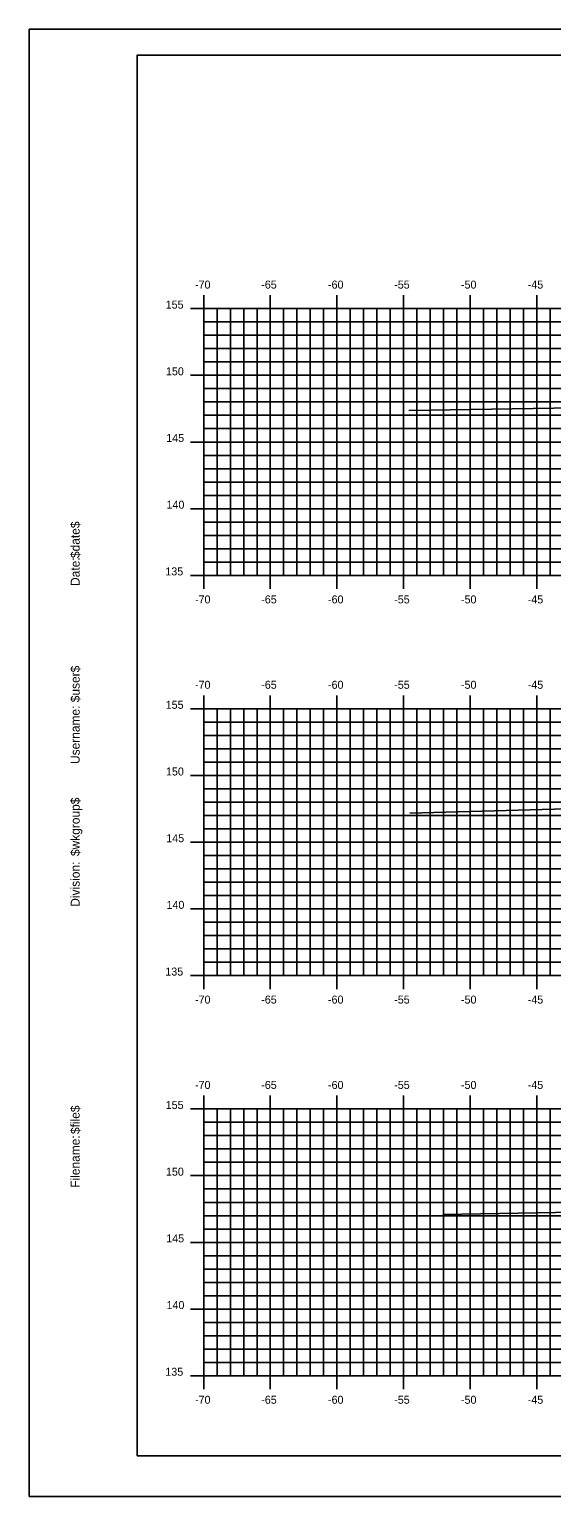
# Model space of a CAD drawing. Extents: x 1146968 to 1147138, y 608981 to 609091.
# Drawn here: x 1146968.1 to 1147007.3, y 608981.3 to 609091.3 of the extents above; entities that cross this region are included whole.
import ezdxf

# ---------------------------------------------------------------- set-up
doc = ezdxf.new("R2010")
doc.units = 0
for name, color, linetype in [('BORDER', 7, 'Continuous'), ('H_V ANNOTATION', 7, 'Continuous'), ('MAJOR', 7, 'Continuous'), ('MINOR', 7, 'Continuous'), ('PLOT BOUNDARY', 7, 'Continuous'), ('S_Roadway_Centerline', 7, 'Continuous')]:
    doc.layers.add(name, color=color, linetype=linetype)

msp = doc.modelspace()

# ---------------------------------------------------------------- linework, layer by layer
at = {"layer": 'BORDER'}
msp.add_lwpolyline([(1146976.18, 608984.34), (1147136.18, 608984.34), (1147136.18, 609089.34), (1146976.18, 609089.34)], close=True, dxfattribs=at)
at = {"layer": 'MAJOR'}
for p, q in [((1146981.18, 609071.34), (1146981.18, 609070.34)), ((1146986.18, 609071.34), (1146986.18, 609070.34)), ((1146991.18, 609071.34), (1146991.18, 609070.34)), ((1146996.18, 609071.34), (1146996.18, 609070.34)), ((1147001.18, 609071.34), (1147001.18, 609070.34)), ((1147006.18, 609071.34), (1147006.18, 609070.34)), ((1146980.18, 609070.34), (1146981.18, 609070.34)), ((1146981.18, 609070.34), (1147121.18, 609070.34)), ((1146981.18, 609050.34), (1146981.18, 609070.34)), ((1146981.18, 609050.34), (1146981.18, 609070.34)), ((1146981.18, 609070.34), (1147121.18, 609070.34)), ((1146986.18, 609050.34), (1146986.18, 609070.34)), ((1146991.18, 609050.34), (1146991.18, 609070.34)), ((1146996.18, 609050.34), (1146996.18, 609070.34)), ((1147001.18, 609050.34), (1147001.18, 609070.34)), ((1147006.18, 609050.34), (1147006.18, 609070.34)), ((1146980.18, 609065.34), (1146981.18, 609065.34)), ((1146981.18, 609065.34), (1147121.18, 609065.34)), ((1146980.18, 609060.34), (1146981.18, 609060.34)), ((1146981.18, 609060.34), (1147121.18, 609060.34)), ((1146980.18, 609055.34), (1146981.18, 609055.34)), ((1146981.18, 609055.34), (1147121.18, 609055.34)), ((1146980.18, 609050.34), (1146981.18, 609050.34)), ((1146981.18, 609050.34), (1147121.18, 609050.34)), ((1146981.18, 609050.34), (1147121.18, 609050.34)), ((1146981.18, 609049.33), (1146981.18, 609050.34)), ((1146986.18, 609049.33), (1146986.18, 609050.34)), ((1146991.18, 609049.33), (1146991.18, 609050.34)), ((1146996.18, 609049.33), (1146996.18, 609050.34)), ((1147001.18, 609049.33), (1147001.18, 609050.34)), ((1147006.18, 609049.33), (1147006.18, 609050.34)), ((1146980.18, 609040.34), (1146981.18, 609040.34)), ((1146981.18, 609041.34), (1146981.18, 609040.34)), ((1146981.18, 609040.34), (1147121.18, 609040.34)), ((1146981.18, 609020.34), (1146981.18, 609040.34)), ((1146981.18, 609020.34), (1146981.18, 609040.34)), ((1146981.18, 609040.34), (1147121.18, 609040.34)), ((1146986.18, 609041.34), (1146986.18, 609040.34)), ((1146986.18, 609020.34), (1146986.18, 609040.34)), ((1146991.18, 609041.34), (1146991.18, 609040.34)), ((1146991.18, 609020.34), (1146991.18, 609040.34)), ((1146996.18, 609041.34), (1146996.18, 609040.34)), ((1146996.18, 609020.34), (1146996.18, 609040.34)), ((1147001.18, 609041.34), (1147001.18, 609040.34)), ((1147001.18, 609020.34), (1147001.18, 609040.34)), ((1147006.18, 609041.34), (1147006.18, 609040.34)), ((1147006.18, 609020.34), (1147006.18, 609040.34)), ((1146980.18, 609035.34), (1146981.18, 609035.34)), ((1146981.18, 609035.34), (1147121.18, 609035.34)), ((1146980.18, 609030.34), (1146981.18, 609030.34)), ((1146981.18, 609030.34), (1147121.18, 609030.34)), ((1146980.18, 609025.34), (1146981.18, 609025.34)), ((1146981.18, 609025.34), (1147121.18, 609025.34)), ((1146980.18, 609020.34), (1146981.18, 609020.34)), ((1146981.18, 609020.34), (1147121.18, 609020.34)), ((1146981.18, 609020.34), (1147121.18, 609020.34)), ((1146981.18, 609019.33), (1146981.18, 609020.34)), ((1146986.18, 609019.33), (1146986.18, 609020.34)), ((1146991.18, 609019.33), (1146991.18, 609020.34)), ((1146996.18, 609019.33), (1146996.18, 609020.34)), ((1147001.18, 609019.33), (1147001.18, 609020.34)), ((1147006.18, 609019.33), (1147006.18, 609020.34)), ((1146981.18, 609011.34), (1146981.18, 609010.34)), ((1146986.18, 609011.34), (1146986.18, 609010.34)), ((1146991.18, 609011.34), (1146991.18, 609010.34)), ((1146996.18, 609011.34), (1146996.18, 609010.34)), ((1147001.18, 609011.34), (1147001.18, 609010.34)), ((1147006.18, 609011.34), (1147006.18, 609010.34)), ((1146980.18, 609010.34), (1146981.18, 609010.34)), ((1146981.18, 609010.34), (1147121.18, 609010.34)), ((1146981.18, 608990.34), (1146981.18, 609010.34)), ((1146981.18, 608990.34), (1146981.18, 609010.34)), ((1146981.18, 609010.34), (1147121.18, 609010.34)), ((1146986.18, 608990.34), (1146986.18, 609010.34)), ((1146991.18, 608990.34), (1146991.18, 609010.34)), ((1146996.18, 608990.34), (1146996.18, 609010.34)), ((1147001.18, 608990.34), (1147001.18, 609010.34)), ((1147006.18, 608990.34), (1147006.18, 609010.34)), ((1146980.18, 609005.34), (1146981.18, 609005.34)), ((1146981.18, 609005.34), (1147121.18, 609005.34)), ((1146980.18, 609000.34), (1146981.18, 609000.34)), ((1146981.18, 609000.34), (1147121.18, 609000.34)), ((1146980.18, 608995.34), (1146981.18, 608995.34)), ((1146981.18, 608995.34), (1147121.18, 608995.34)), ((1146980.18, 608990.34), (1146981.18, 608990.34)), ((1146981.18, 608990.34), (1147121.18, 608990.34)), ((1146981.18, 608990.34), (1147121.18, 608990.34)), ((1146981.18, 608989.33), (1146981.18, 608990.34)), ((1146986.18, 608989.33), (1146986.18, 608990.34)), ((1146991.18, 608989.33), (1146991.18, 608990.34)), ((1146996.18, 608989.33), (1146996.18, 608990.34)), ((1147001.18, 608989.33), (1147001.18, 608990.34)), ((1147006.18, 608989.33), (1147006.18, 608990.34))]:
    msp.add_line(p, q, dxfattribs=at)
at = {"layer": 'MINOR'}
for p, q in [((1146982.18, 609050.34), (1146982.18, 609070.34)), ((1146983.18, 609050.34), (1146983.18, 609070.34)), ((1146984.18, 609050.34), (1146984.18, 609070.34)), ((1146985.18, 609050.34), (1146985.18, 609070.34)), ((1146987.18, 609050.34), (1146987.18, 609070.34)), ((1146988.18, 609050.34), (1146988.18, 609070.34)), ((1146989.18, 609050.34), (1146989.18, 609070.34)), ((1146990.18, 609050.34), (1146990.18, 609070.34)), ((1146992.18, 609050.34), (1146992.18, 609070.34)), ((1146993.18, 609050.34), (1146993.18, 609070.34)), ((1146994.18, 609050.34), (1146994.18, 609070.34)), ((1146995.18, 609050.34), (1146995.18, 609070.34)), ((1146997.18, 609050.34), (1146997.18, 609070.34)), ((1146998.18, 609050.34), (1146998.18, 609070.34)), ((1146999.18, 609050.34), (1146999.18, 609070.34)), ((1147000.18, 609050.34), (1147000.18, 609070.34)), ((1147002.18, 609050.34), (1147002.18, 609070.34)), ((1147003.18, 609050.34), (1147003.18, 609070.34)), ((1147004.18, 609050.34), (1147004.18, 609070.34)), ((1147005.18, 609050.34), (1147005.18, 609070.34)), ((1147007.18, 609050.34), (1147007.18, 609070.34)), ((1146981.18, 609069.34), (1147121.18, 609069.34)), ((1146981.18, 609069.34), (1146982.19, 609069.34)), ((1146981.18, 609068.34), (1147121.18, 609068.34)), ((1146981.18, 609068.34), (1146982.19, 609068.34)), ((1146981.18, 609067.34), (1147121.18, 609067.34)), ((1146981.18, 609067.34), (1146982.19, 609067.34)), ((1146981.18, 609066.34), (1147121.18, 609066.34)), ((1146981.18, 609066.34), (1146982.19, 609066.34)), ((1146981.18, 609064.34), (1147121.18, 609064.34)), ((1146981.18, 609064.34), (1146982.19, 609064.34)), ((1146981.18, 609063.34), (1147121.18, 609063.34)), ((1146981.18, 609063.34), (1146982.19, 609063.34)), ((1146981.18, 609062.34), (1147121.18, 609062.34)), ((1146981.18, 609062.34), (1146982.19, 609062.34)), ((1146981.18, 609061.34), (1147121.18, 609061.34)), ((1146981.18, 609061.34), (1146982.19, 609061.34)), ((1146981.18, 609059.34), (1147121.18, 609059.34)), ((1146981.18, 609059.34), (1146982.19, 609059.34)), ((1146981.18, 609058.34), (1147121.18, 609058.34)), ((1146981.18, 609058.34), (1146982.19, 609058.34)), ((1146981.18, 609057.34), (1147121.18, 609057.34)), ((1146981.18, 609057.34), (1146982.19, 609057.34)), ((1146981.18, 609056.34), (1147121.18, 609056.34)), ((1146981.18, 609056.34), (1146982.19, 609056.34)), ((1146981.18, 609054.34), (1147121.18, 609054.34)), ((1146981.18, 609054.34), (1146982.19, 609054.34)), ((1146981.18, 609053.34), (1147121.18, 609053.34)), ((1146981.18, 609053.34), (1146982.19, 609053.34)), ((1146981.18, 609052.34), (1147121.18, 609052.34)), ((1146981.18, 609052.34), (1146982.19, 609052.34)), ((1146981.18, 609051.34), (1147121.18, 609051.34)), ((1146981.18, 609051.34), (1146982.19, 609051.34)), ((1146982.18, 609020.34), (1146982.18, 609040.34)), ((1146983.18, 609020.34), (1146983.18, 609040.34)), ((1146984.18, 609020.34), (1146984.18, 609040.34)), ((1146985.18, 609020.34), (1146985.18, 609040.34)), ((1146987.18, 609020.34), (1146987.18, 609040.34)), ((1146988.18, 609020.34), (1146988.18, 609040.34)), ((1146989.18, 609020.34), (1146989.18, 609040.34)), ((1146990.18, 609020.34), (1146990.18, 609040.34)), ((1146992.18, 609020.34), (1146992.18, 609040.34)), ((1146993.18, 609020.34), (1146993.18, 609040.34)), ((1146994.18, 609020.34), (1146994.18, 609040.34)), ((1146995.18, 609020.34), (1146995.18, 609040.34)), ((1146997.18, 609020.34), (1146997.18, 609040.34)), ((1146998.18, 609020.34), (1146998.18, 609040.34)), ((1146999.18, 609020.34), (1146999.18, 609040.34)), ((1147000.18, 609020.34), (1147000.18, 609040.34)), ((1147002.18, 609020.34), (1147002.18, 609040.34)), ((1147003.18, 609020.34), (1147003.18, 609040.34)), ((1147004.18, 609020.34), (1147004.18, 609040.34)), ((1147005.18, 609020.34), (1147005.18, 609040.34)), ((1147007.18, 609020.34), (1147007.18, 609040.34)), ((1146981.18, 609039.34), (1147121.18, 609039.34)), ((1146981.18, 609039.34), (1146982.19, 609039.34)), ((1146981.18, 609038.34), (1147121.18, 609038.34)), ((1146981.18, 609038.34), (1146982.19, 609038.34)), ((1146981.18, 609037.34), (1147121.18, 609037.34)), ((1146981.18, 609037.34), (1146982.19, 609037.34)), ((1146981.18, 609036.34), (1147121.18, 609036.34)), ((1146981.18, 609036.34), (1146982.19, 609036.34)), ((1146981.18, 609034.34), (1147121.18, 609034.34)), ((1146981.18, 609034.34), (1146982.19, 609034.34)), ((1146981.18, 609033.34), (1147121.18, 609033.34)), ((1146981.18, 609033.34), (1146982.19, 609033.34)), ((1146981.18, 609032.34), (1147121.18, 609032.34)), ((1146981.18, 609032.34), (1146982.19, 609032.34)), ((1146981.18, 609031.34), (1147121.18, 609031.34)), ((1146981.18, 609031.34), (1146982.19, 609031.34)), ((1146981.18, 609029.34), (1147121.18, 609029.34)), ((1146981.18, 609029.34), (1146982.19, 609029.34)), ((1146981.18, 609028.34), (1147121.18, 609028.34)), ((1146981.18, 609028.34), (1146982.19, 609028.34)), ((1146981.18, 609027.34), (1147121.18, 609027.34)), ((1146981.18, 609027.34), (1146982.19, 609027.34)), ((1146981.18, 609026.34), (1147121.18, 609026.34)), ((1146981.18, 609026.34), (1146982.19, 609026.34)), ((1146981.18, 609024.34), (1147121.18, 609024.34)), ((1146981.18, 609024.34), (1146982.19, 609024.34)), ((1146981.18, 609023.34), (1147121.18, 609023.34)), ((1146981.18, 609023.34), (1146982.19, 609023.34)), ((1146981.18, 609022.34), (1147121.18, 609022.34)), ((1146981.18, 609022.34), (1146982.19, 609022.34)), ((1146981.18, 609021.34), (1147121.18, 609021.34)), ((1146981.18, 609021.34), (1146982.19, 609021.34)), ((1146982.18, 608990.34), (1146982.18, 609010.34)), ((1146983.18, 608990.34), (1146983.18, 609010.34)), ((1146984.18, 608990.34), (1146984.18, 609010.34)), ((1146985.18, 608990.34), (1146985.18, 609010.34)), ((1146987.18, 608990.34), (1146987.18, 609010.34)), ((1146988.18, 608990.34), (1146988.18, 609010.34)), ((1146989.18, 608990.34), (1146989.18, 609010.34)), ((1146990.18, 608990.34), (1146990.18, 609010.34)), ((1146992.18, 608990.34), (1146992.18, 609010.34)), ((1146993.18, 608990.34), (1146993.18, 609010.34)), ((1146994.18, 608990.34), (1146994.18, 609010.34)), ((1146995.18, 608990.34), (1146995.18, 609010.34)), ((1146997.18, 608990.34), (1146997.18, 609010.34)), ((1146998.18, 608990.34), (1146998.18, 609010.34)), ((1146999.18, 608990.34), (1146999.18, 609010.34)), ((1147000.18, 608990.34), (1147000.18, 609010.34)), ((1147002.18, 608990.34), (1147002.18, 609010.34)), ((1147003.18, 608990.34), (1147003.18, 609010.34)), ((1147004.18, 608990.34), (1147004.18, 609010.34)), ((1147005.18, 608990.34), (1147005.18, 609010.34)), ((1147007.18, 608990.34), (1147007.18, 609010.34)), ((1146981.18, 609009.34), (1147121.18, 609009.34)), ((1146981.18, 609009.34), (1146982.19, 609009.34)), ((1146981.18, 609008.34), (1147121.18, 609008.34)), ((1146981.18, 609008.34), (1146982.19, 609008.34)), ((1146981.18, 609007.34), (1147121.18, 609007.34)), ((1146981.18, 609007.34), (1146982.19, 609007.34)), ((1146981.18, 609006.34), (1147121.18, 609006.34)), ((1146981.18, 609006.34), (1146982.19, 609006.34)), ((1146981.18, 609004.34), (1147121.18, 609004.34)), ((1146981.18, 609004.34), (1146982.19, 609004.34)), ((1146981.18, 609003.34), (1147121.18, 609003.34)), ((1146981.18, 609003.34), (1146982.19, 609003.34)), ((1146981.18, 609002.34), (1147121.18, 609002.34)), ((1146981.18, 609002.34), (1146982.19, 609002.34)), ((1146981.18, 609001.34), (1147121.18, 609001.34)), ((1146981.18, 609001.34), (1146982.19, 609001.34)), ((1146981.18, 608999.34), (1147121.18, 608999.34)), ((1146981.18, 608999.34), (1146982.19, 608999.34)), ((1146981.18, 608998.34), (1147121.18, 608998.34)), ((1146981.18, 608998.34), (1146982.19, 608998.34)), ((1146981.18, 608997.34), (1147121.18, 608997.34)), ((1146981.18, 608997.34), (1146982.19, 608997.34)), ((1146981.18, 608996.34), (1147121.18, 608996.34)), ((1146981.18, 608996.34), (1146982.19, 608996.34)), ((1146981.18, 608994.34), (1147121.18, 608994.34)), ((1146981.18, 608994.34), (1146982.19, 608994.34)), ((1146981.18, 608993.34), (1147121.18, 608993.34)), ((1146981.18, 608993.34), (1146982.19, 608993.34)), ((1146981.18, 608992.34), (1147121.18, 608992.34)), ((1146981.18, 608992.34), (1146982.19, 608992.34)), ((1146981.18, 608991.34), (1147121.18, 608991.34)), ((1146981.18, 608991.34), (1146982.19, 608991.34))]:
    msp.add_line(p, q, dxfattribs=at)
at = {"layer": 'PLOT BOUNDARY'}
msp.add_lwpolyline([(1146968.09, 608981.28), (1147138.09, 608981.28), (1147138.09, 609091.28), (1146968.09, 609091.28)], close=True, dxfattribs=at)
at = {"layer": 'S_Roadway_Centerline'}
for points in [[(1146996.58, 609062.7), (1147013.65, 609062.97)], [(1146996.65, 609032.51), (1147017.43, 609033.09)], [(1146999.15, 609002.42), (1147023.04, 609002.86)]]:
    msp.add_lwpolyline(points, dxfattribs=at)

# ---------------------------------------------------------------- texts
at = {"layer": 'BORDER'}
for s, p in [('$date$', (1146971.87, 609051.64)), ('Date:', (1146971.87, 609049.55)), ('$user$', (1146971.87, 609040.83)), ('Username:', (1146971.87, 609036.2)), ('$wkgroup$', (1146971.87, 609029.3)), ('Division:', (1146971.87, 609025.5)), ('$file$', (1146971.87, 609008.46)), ('Filename:', (1146971.87, 609004.43))]:
    msp.add_text(s, height=0.67, rotation=90, dxfattribs=at).set_placement(p)
at = {"layer": 'H_V ANNOTATION'}
for s, p in [('-70', (1146980.53, 609071.84)), ('-65', (1146985.5, 609071.84)), ('-60', (1146990.51, 609071.84)), ('-55', (1146995.48, 609071.84)), ('-50', (1147000.49, 609071.84)), ('-45', (1147005.5, 609071.84)), ('155', (1146978.33, 609070.34)), ('150', (1146978.35, 609065.34)), ('145', (1146978.37, 609060.34)), ('140', (1146978.39, 609055.34)), ('135', (1146978.3, 609050.34)), ('-70', (1146980.53, 609048.24)), ('-65', (1146985.5, 609048.24)), ('-60', (1146990.51, 609048.24)), ('-55', (1146995.48, 609048.24)), ('-50', (1147000.49, 609048.24)), ('-45', (1147005.5, 609048.24)), ('-70', (1146980.53, 609041.84)), ('-65', (1146985.5, 609041.84)), ('-60', (1146990.51, 609041.84)), ('-55', (1146995.48, 609041.84)), ('-50', (1147000.49, 609041.84)), ('-45', (1147005.5, 609041.84)), ('155', (1146978.33, 609040.34)), ('150', (1146978.35, 609035.34)), ('145', (1146978.37, 609030.34)), ('140', (1146978.39, 609025.34)), ('135', (1146978.3, 609020.34)), ('-70', (1146980.53, 609018.24)), ('-65', (1146985.5, 609018.24)), ('-60', (1146990.51, 609018.24)), ('-55', (1146995.48, 609018.24)), ('-50', (1147000.49, 609018.24)), ('-45', (1147005.5, 609018.24)), ('-70', (1146980.53, 609011.84)), ('-65', (1146985.5, 609011.84)), ('-60', (1146990.51, 609011.84)), ('-55', (1146995.48, 609011.84)), ('-50', (1147000.49, 609011.84)), ('-45', (1147005.5, 609011.84)), ('155', (1146978.33, 609010.34)), ('150', (1146978.35, 609005.34)), ('145', (1146978.37, 609000.34)), ('140', (1146978.39, 608995.34)), ('135', (1146978.3, 608990.34)), ('-70', (1146980.53, 608988.24)), ('-65', (1146985.5, 608988.24)), ('-60', (1146990.51, 608988.24)), ('-55', (1146995.48, 608988.24)), ('-50', (1147000.49, 608988.24)), ('-45', (1147005.5, 608988.24))]:
    msp.add_text(s, height=0.6, dxfattribs=at).set_placement(p)
at = {"layer": 'MAJOR'}
for p in [(1146981.18, 609050.34), (1146981.18, 609020.34), (1146981.18, 608990.34)]:
    msp.add_text('-', height=0.006, dxfattribs=at).set_placement(p)

doc.saveas('drawing.dxf')
